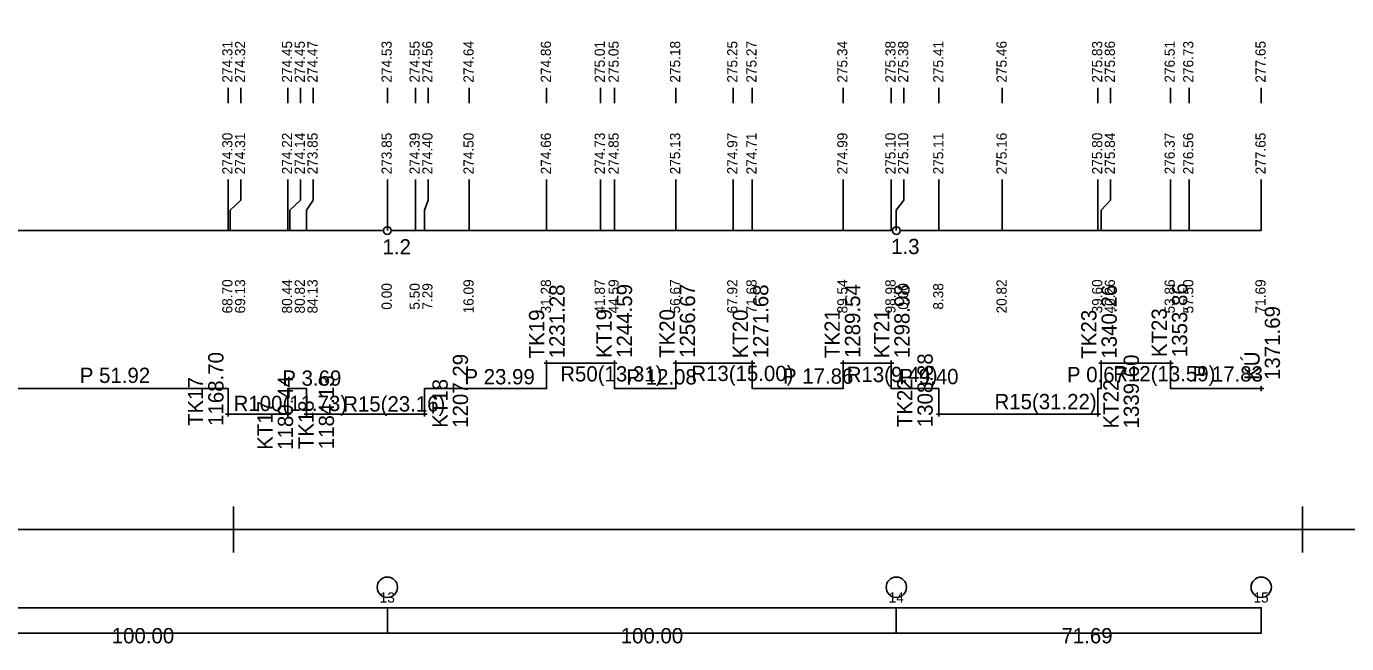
# Model space of a CAD drawing. Extents: x 1531 to 1699, y 61 to 93.
# Drawn here: x 1652.6 to 1678.54, y 60.9 to 73.01 of the extents above; entities that cross this region are included whole.
import ezdxf

# ---------------------------------------------------------------- set-up
doc = ezdxf.new("R2010")
doc.units = 0
for name, color, linetype in [('SESTAVY_REZU_PO', 7, 'Continuous'), ('SMEROVE_POMERY', 7, 'Continuous'), ('SMEROVE_POMERY_KOD', 7, 'Continuous'), ('SVK_STAT', 7, 'Continuous'), ('u_pricne_rezy', 7, 'Continuous'), ('x_formát_rám', 7, 'Continuous')]:
    doc.layers.add(name, color=color, linetype=linetype)

msp = doc.modelspace()

# ---------------------------------------------------------------- linework, layer by layer
at = {"layer": 'SESTAVY_REZU_PO'}
for points in [[(1649.769, 69), (1659.619, 69)], [(1659.769, 69), (1669.619, 69)], [(1669.769, 69), (1676.863, 69)]]:
    msp.add_lwpolyline(points, dxfattribs=at)
for centre in [(1659.694, 69), (1669.694, 69)]:
    msp.add_circle(centre, 0.075, dxfattribs=at)
at = {"layer": 'SMEROVE_POMERY'}
msp.add_lwpolyline([(1651.373, 65.899), (1656.565, 65.899), (1656.565, 65.399), (1657.738, 65.399), (1657.738, 65.899), (1658.107, 65.899), (1658.107, 65.399), (1660.424, 65.399), (1660.424, 65.899), (1662.822, 65.899), (1662.822, 66.399), (1664.154, 66.399), (1664.154, 65.899), (1665.362, 65.899), (1665.362, 66.399), (1666.862, 66.399), (1666.862, 65.899), (1668.648, 65.899), (1668.648, 66.399), (1669.592, 66.399), (1669.592, 65.899), (1670.532, 65.899), (1670.532, 65.399), (1673.654, 65.399), (1673.654, 65.899), (1673.721, 65.899), (1673.721, 66.399), (1675.08, 66.399), (1675.08, 65.899), (1676.863, 65.899)], dxfattribs=at)
at = {"layer": 'SMEROVE_POMERY_KOD'}
for points in [[(1662.822, 66.349), (1662.822, 66.449)], [(1664.154, 66.349), (1664.154, 66.449)], [(1665.362, 66.349), (1665.362, 66.449)], [(1666.862, 66.349), (1666.862, 66.449)], [(1668.648, 66.349), (1668.648, 66.449)], [(1669.592, 66.349), (1669.592, 66.449)], [(1673.721, 66.349), (1673.721, 66.449)], [(1675.08, 66.349), (1675.08, 66.449)], [(1662.772, 66.399), (1662.872, 66.399)], [(1664.104, 66.399), (1664.204, 66.399)], [(1665.312, 66.399), (1665.412, 66.399)], [(1666.812, 66.399), (1666.912, 66.399)], [(1668.598, 66.399), (1668.698, 66.399)], [(1669.542, 66.399), (1669.642, 66.399)], [(1673.671, 66.399), (1673.771, 66.399)], [(1675.03, 66.399), (1675.13, 66.399)], [(1676.813, 65.899), (1676.913, 65.899)], [(1676.863, 65.849), (1676.863, 65.949)], [(1656.515, 65.399), (1656.615, 65.399)], [(1656.565, 65.349), (1656.565, 65.449)], [(1657.688, 65.399), (1657.788, 65.399)], [(1657.738, 65.349), (1657.738, 65.449)], [(1658.057, 65.399), (1658.157, 65.399)], [(1658.107, 65.349), (1658.107, 65.449)], [(1660.374, 65.399), (1660.474, 65.399)], [(1660.424, 65.349), (1660.424, 65.449)], [(1670.482, 65.399), (1670.582, 65.399)], [(1670.532, 65.349), (1670.532, 65.449)], [(1673.604, 65.399), (1673.704, 65.399)], [(1673.654, 65.349), (1673.654, 65.449)]]:
    msp.add_lwpolyline(points, dxfattribs=at)
at = {"layer": 'SVK_STAT'}
for points in [[(1656.565, 71.5), (1656.565, 71.8)], [(1656.815, 71.5), (1656.815, 71.8)], [(1657.738, 71.5), (1657.738, 71.8)], [(1657.988, 71.5), (1657.988, 71.8)], [(1658.238, 71.5), (1658.238, 71.8)], [(1659.694, 71.5), (1659.694, 71.8)], [(1660.245, 71.5), (1660.245, 71.8)], [(1660.495, 71.5), (1660.495, 71.8)], [(1661.303, 71.5), (1661.303, 71.8)], [(1662.822, 71.5), (1662.822, 71.8)], [(1663.882, 71.5), (1663.882, 71.8)], [(1664.154, 71.5), (1664.154, 71.8)], [(1665.362, 71.5), (1665.362, 71.8)], [(1666.486, 71.5), (1666.486, 71.8)], [(1666.862, 71.5), (1666.862, 71.8)], [(1668.648, 71.5), (1668.648, 71.8)], [(1669.592, 71.5), (1669.592, 71.8)], [(1669.842, 71.5), (1669.842, 71.8)], [(1670.532, 71.5), (1670.532, 71.8)], [(1671.776, 71.5), (1671.776, 71.8)], [(1673.654, 71.5), (1673.654, 71.8)], [(1673.904, 71.5), (1673.904, 71.8)], [(1675.08, 71.5), (1675.08, 71.8)], [(1675.445, 71.5), (1675.445, 71.8)], [(1676.863, 71.5), (1676.863, 71.8)], [(1656.565, 69), (1656.565, 70)], [(1656.608, 69), (1656.608, 69.4), (1656.815, 69.6), (1656.815, 70)], [(1657.738, 69), (1657.738, 70)], [(1657.777, 69), (1657.777, 69.4), (1657.988, 69.6), (1657.988, 70)], [(1658.107, 69), (1658.107, 69.4), (1658.238, 69.6), (1658.238, 70)], [(1659.694, 69), (1659.694, 70)], [(1660.245, 69), (1660.245, 70)], [(1660.424, 69), (1660.424, 69.4), (1660.495, 69.6), (1660.495, 70)], [(1661.303, 69), (1661.303, 70)], [(1662.822, 69), (1662.822, 70)], [(1663.882, 69), (1663.882, 70)], [(1664.154, 69), (1664.154, 70)], [(1665.362, 69), (1665.362, 70)], [(1666.486, 69), (1666.486, 70)], [(1666.862, 69), (1666.862, 70)], [(1668.648, 69), (1668.648, 70)], [(1669.592, 69), (1669.592, 70)], [(1669.694, 69), (1669.694, 69.4), (1669.842, 69.6), (1669.842, 70)], [(1670.532, 69), (1670.532, 70)], [(1671.776, 69), (1671.776, 70)], [(1673.654, 69), (1673.654, 70)], [(1673.721, 69), (1673.721, 69.4), (1673.904, 69.6), (1673.904, 70)], [(1675.08, 69), (1675.08, 70)], [(1675.445, 69), (1675.445, 70)], [(1676.863, 69), (1676.863, 70)]]:
    msp.add_lwpolyline(points, dxfattribs=at)
at = {"layer": 'u_pricne_rezy'}
for points in [[(1539.694, 61.1), (1676.863, 61.1), (1676.863, 61.6), (1539.694, 61.6), (1539.694, 61.1)], [(1659.694, 61.1), (1659.694, 61.6)], [(1669.694, 61.1), (1669.694, 61.6)]]:
    msp.add_lwpolyline(points, dxfattribs=at)
for centre in [(1659.694, 62), (1669.694, 62), (1676.863, 62)]:
    msp.add_circle(centre, 0.2, dxfattribs=at)
at = {"layer": 'x_formát_rám'}
for p, q in [((1656.673, 63.586), (1656.673, 62.686)), ((1677.673, 63.586), (1677.673, 62.686))]:
    msp.add_line(p, q, dxfattribs=at)
msp.add_lwpolyline([(1530.673, 63.136), (1698.673, 63.136), (1698.673, 92.836), (1530.673, 92.836)], close=True, dxfattribs=at)

# ---------------------------------------------------------------- texts
at = {"layer": 'SESTAVY_REZU_PO'}
for s, p in [('1.2', (1659.599, 68.532)), ('1.3', (1669.593, 68.539))]:
    msp.add_text(s, height=0.3, dxfattribs=at).set_placement(p)
at = {"layer": 'SMEROVE_POMERY'}
for s, p in [('P 51.92', (1653.651, 66.01)), ('P 3.69', (1657.63, 65.956)), ('P 23.99', (1661.208, 65.983)), ('R50(13.31)', (1663.091, 66.039)), ('P 12.08', (1664.391, 65.98)), ('R13(15.00)', (1665.666, 66.048)), ('P 17.86', (1667.467, 65.995)), ('R13(9.44)', (1668.719, 66.027)), ('P 9.40', (1669.756, 65.986)), ('P 0.67', (1673.046, 66.025)), ('R12(13.59)', (1673.955, 66.042)), ('P 17.83', (1675.514, 66.038)), ('R100(11.73)', (1656.673, 65.459)), ('R15(23.16)', (1658.826, 65.45)), ('R15(31.22)', (1671.623, 65.495))]:
    msp.add_text(s, height=0.3, dxfattribs=at).set_placement(p)
at = {"layer": 'SMEROVE_POMERY_KOD'}
for s, p in [('1231.28', (1663.176, 66.493)), ('1244.59', (1664.502, 66.502)), ('1256.67', (1665.74, 66.502)), ('1271.68', (1667.179, 66.493)), ('1289.54', (1668.984, 66.499)), ('1298.98', (1669.955, 66.496)), ('1340.26', (1674.026, 66.487)), ('1353.86', (1675.409, 66.517)), ('KT19', (1664.102, 66.502)), ('TK20', (1665.34, 66.502)), ('KT23', (1675.009, 66.517)), ('1371.69', (1677.232, 66.069)), ('TK19', (1662.776, 66.493)), ('KT20', (1666.779, 66.493)), ('TK21', (1668.584, 66.499)), ('KT21', (1669.555, 66.496)), ('TK23', (1673.626, 66.487)), ('1168.70', (1656.474, 65.167)), ('1207.29', (1661.279, 65.13)), ('1308.38', (1670.409, 65.142)), ('1339.60', (1674.461, 65.118)), ('KÚ', (1676.832, 66.069)), ('TK17', (1656.074, 65.167)), ('1180.44', (1657.841, 64.698)), ('1184.13', (1658.646, 64.71)), ('KT18', (1660.879, 65.13)), ('TK22', (1670.009, 65.142)), ('KT22', (1674.061, 65.118)), ('KT17', (1657.441, 64.698)), ('TK18', (1658.246, 64.71))]:
    msp.add_text(s, height=0.3, rotation=90, dxfattribs=at).set_placement(p)
at = {"layer": 'SVK_STAT'}
for s, p in [(' 274.31', (1656.65, 71.83)), (' 274.32', (1656.9, 71.83)), (' 274.45', (1657.823, 71.83)), (' 274.45', (1658.073, 71.83)), (' 274.47', (1658.323, 71.83)), (' 274.53', (1659.78, 71.83)), (' 274.55', (1660.33, 71.83)), (' 274.56', (1660.58, 71.83)), (' 274.64', (1661.389, 71.83)), (' 274.86', (1662.908, 71.83)), (' 275.01', (1663.967, 71.83)), (' 275.05', (1664.239, 71.83)), (' 275.18', (1665.447, 71.83)), (' 275.25', (1666.571, 71.83)), (' 275.27', (1666.947, 71.83)), (' 275.34', (1668.733, 71.83)), (' 275.38', (1669.678, 71.83)), (' 275.38', (1669.928, 71.83)), (' 275.41', (1670.618, 71.83)), (' 275.46', (1671.862, 71.83)), (' 275.83', (1673.739, 71.83)), (' 275.86', (1673.989, 71.83)), (' 276.51', (1675.165, 71.83)), (' 276.73', (1675.53, 71.83)), (' 277.65', (1676.949, 71.83)), (' 274.30', (1656.65, 70.03)), (' 274.31', (1656.9, 70.03)), (' 274.22', (1657.823, 70.03)), (' 274.14', (1658.073, 70.03)), (' 273.85', (1658.323, 70.03)), (' 273.85', (1659.78, 70.03)), (' 274.39', (1660.33, 70.03)), (' 274.40', (1660.58, 70.03)), (' 274.50', (1661.389, 70.03)), (' 274.66', (1662.908, 70.03)), (' 274.73', (1663.967, 70.03)), (' 274.85', (1664.239, 70.03)), (' 275.13', (1665.447, 70.03)), (' 274.97', (1666.571, 70.03)), (' 274.71', (1666.947, 70.03)), (' 274.99', (1668.733, 70.03)), (' 275.10', (1669.678, 70.03)), (' 275.10', (1669.928, 70.03)), (' 275.11', (1670.618, 70.03)), (' 275.16', (1671.862, 70.03)), (' 275.80', (1673.739, 70.03)), (' 275.84', (1673.989, 70.03)), (' 276.37', (1675.165, 70.03)), (' 276.56', (1675.53, 70.03)), (' 277.65', (1676.949, 70.03)), (' 68.70', (1656.65, 67.3)), (' 69.13', (1656.9, 67.3)), (' 80.44', (1657.823, 67.3)), (' 80.82', (1658.073, 67.3)), (' 84.13', (1658.323, 67.3)), (' 16.09', (1661.389, 67.3)), (' 31.28', (1662.908, 67.3)), (' 41.87', (1663.967, 67.3)), (' 44.59', (1664.239, 67.3)), (' 56.67', (1665.447, 67.3)), (' 67.92', (1666.571, 67.3)), (' 71.68', (1666.947, 67.3)), (' 89.54', (1668.733, 67.3)), (' 98.98', (1669.678, 67.3)), (' 20.82', (1671.862, 67.3)), (' 39.60', (1673.739, 67.3)), (' 40.26', (1673.989, 67.3)), (' 53.86', (1675.165, 67.3)), (' 57.50', (1675.53, 67.3)), (' 71.69', (1676.949, 67.3)), ('  0.00', (1659.78, 67.3)), ('  5.50', (1660.33, 67.3)), ('  7.29', (1660.58, 67.3)), ('  0.00', (1669.928, 67.3)), ('  8.38', (1670.618, 67.3))]:
    msp.add_text(s, height=0.2, rotation=90, dxfattribs=at).set_placement(p)
at = {"layer": 'u_pricne_rezy'}
for s, height, p in [('13', 0.2, (1659.544, 61.7)), ('14', 0.2, (1669.544, 61.7)), ('15', 0.2, (1676.712, 61.7)), ('100.00', 0.3, (1654.279, 60.9)), ('100.00', 0.3, (1664.279, 60.9)), ('71.69', 0.3, (1672.939, 60.9))]:
    msp.add_text(s, height=height, dxfattribs=at).set_placement(p)

doc.saveas('drawing.dxf')
